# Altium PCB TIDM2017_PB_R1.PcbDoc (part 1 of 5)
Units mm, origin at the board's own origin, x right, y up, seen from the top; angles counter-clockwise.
Board outline 120 x 147.5 mm, 4 copper layers (Top Layer, L2, L3, Bottom Layer), stack 1.413 mm thick; 117 components, 53 nets, 3137 pads, 96 vias.
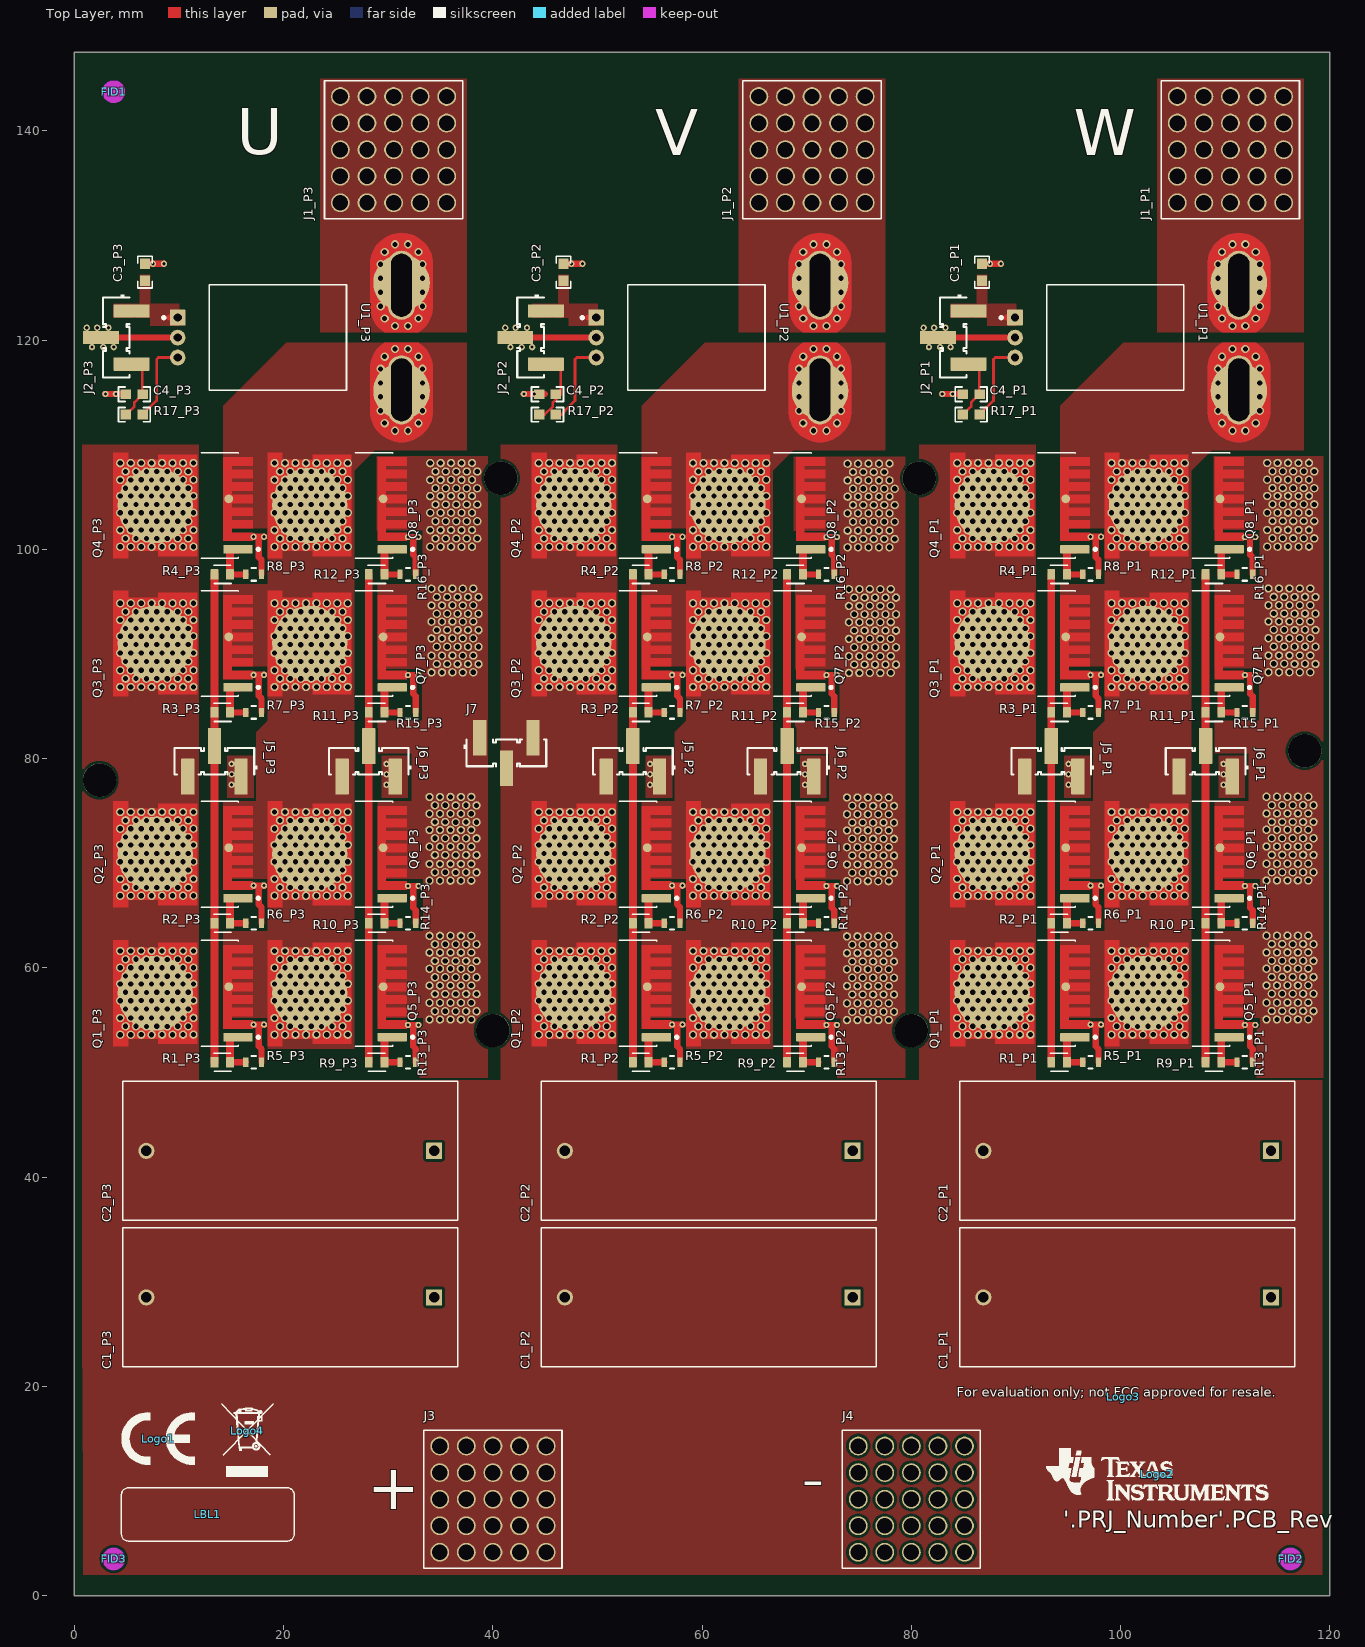
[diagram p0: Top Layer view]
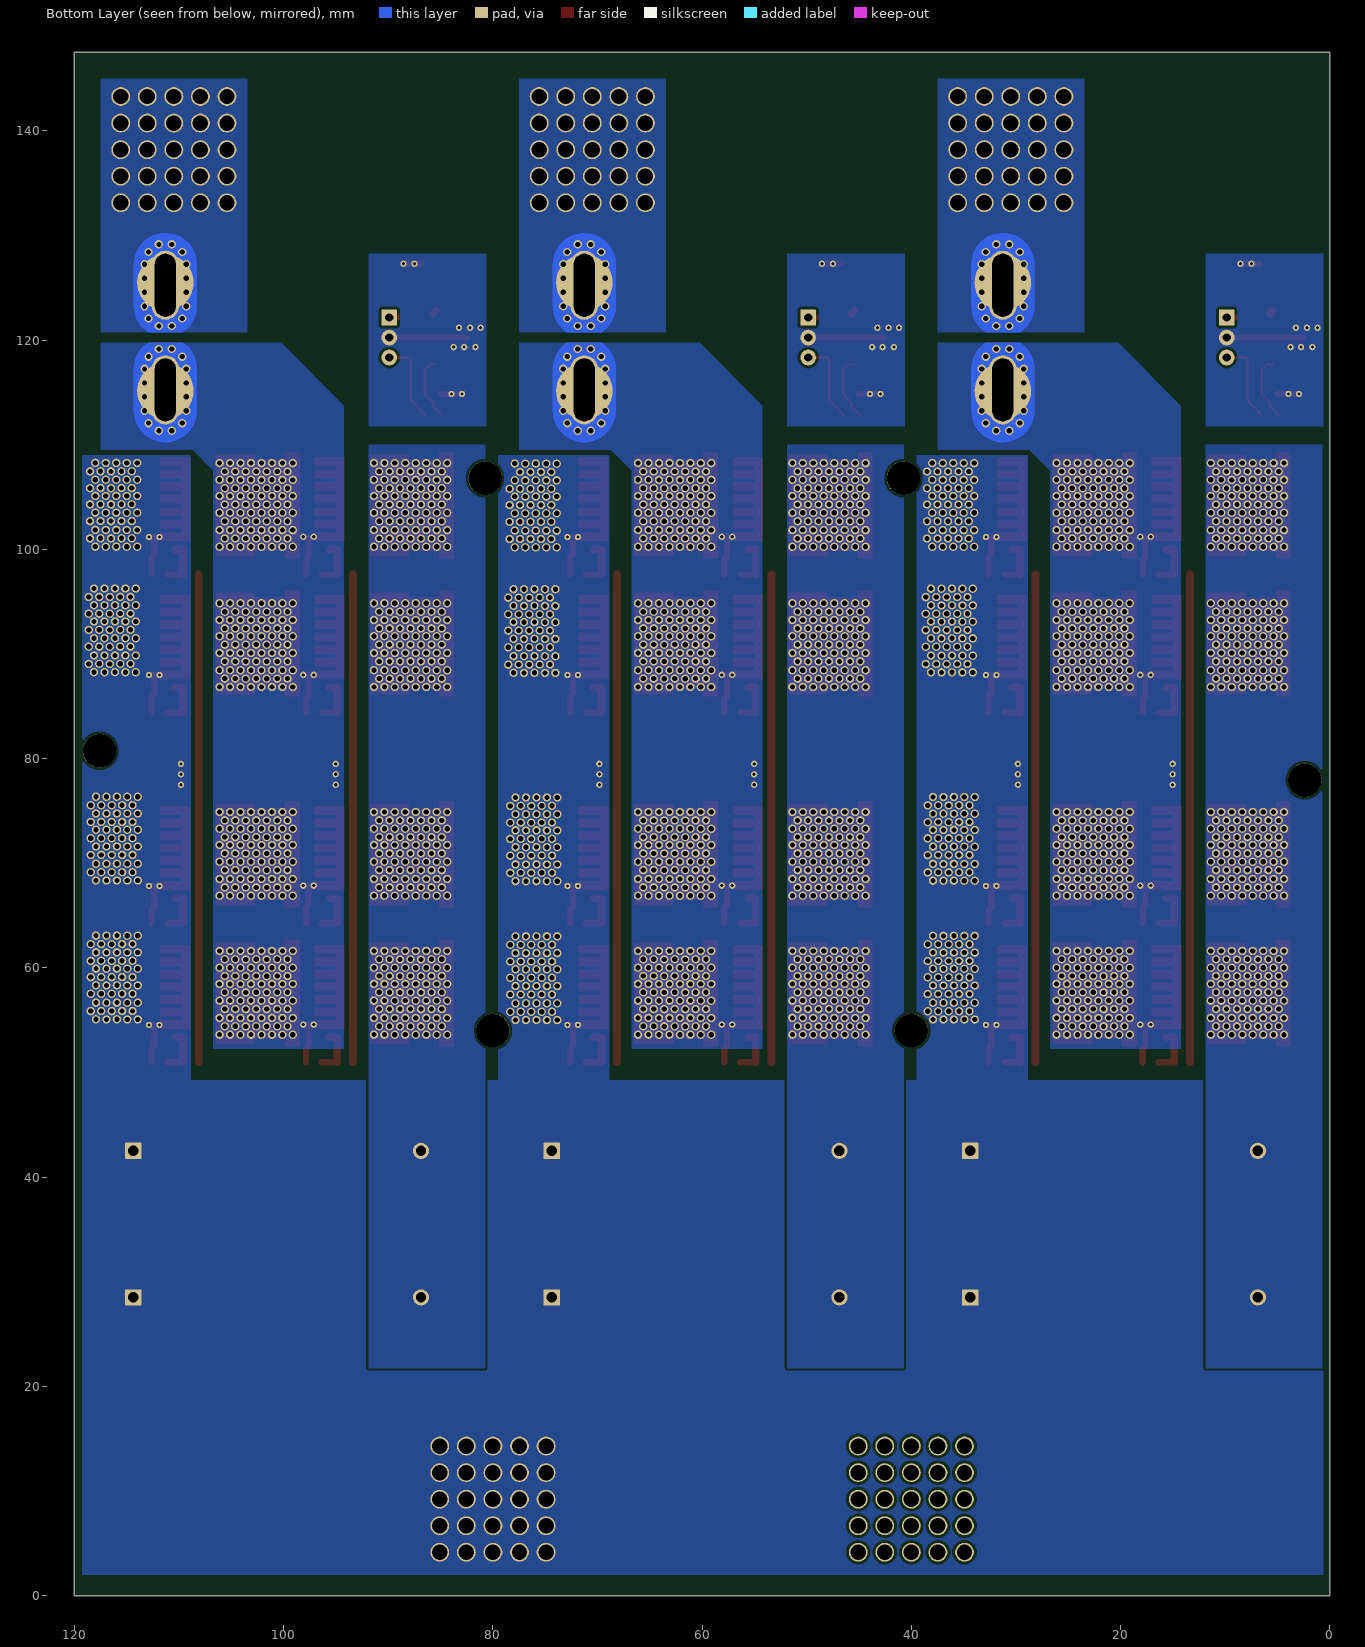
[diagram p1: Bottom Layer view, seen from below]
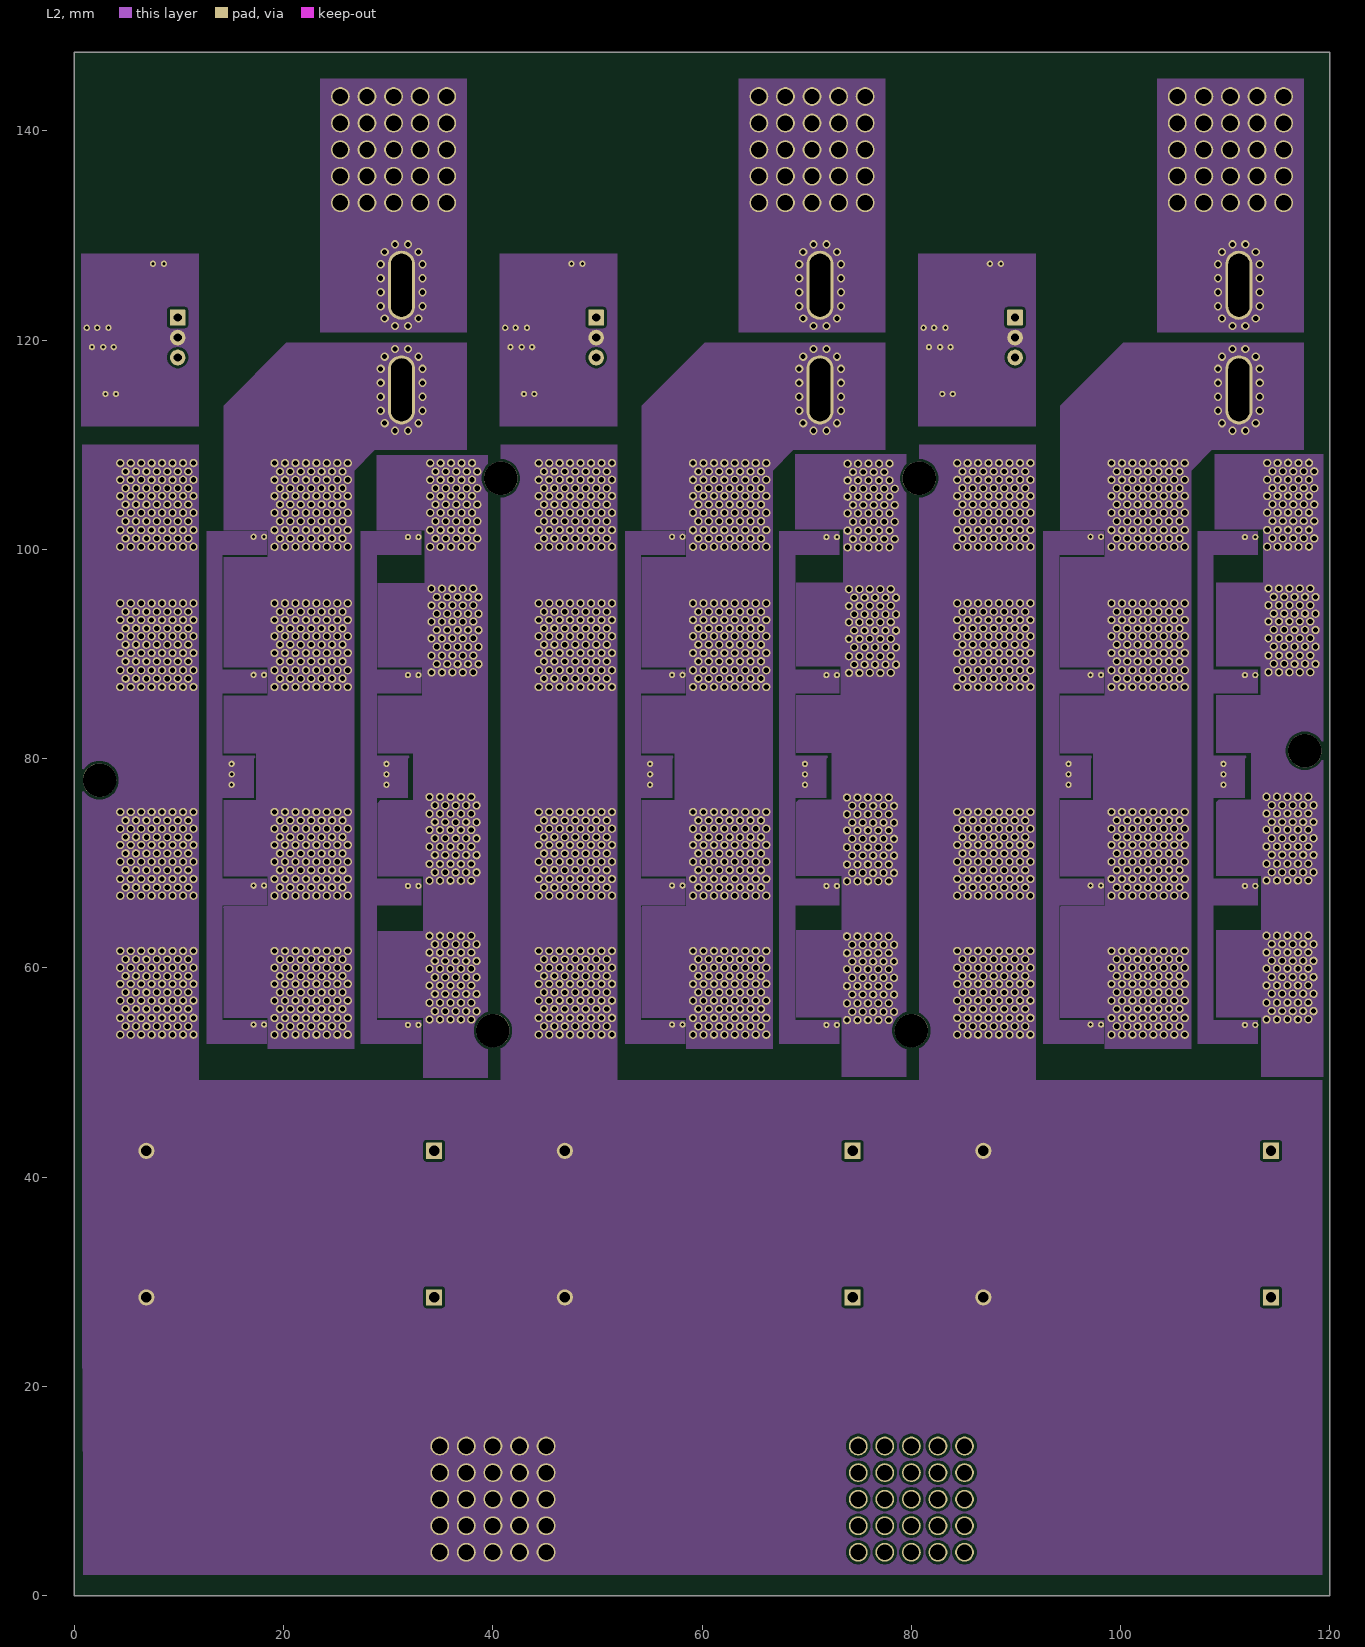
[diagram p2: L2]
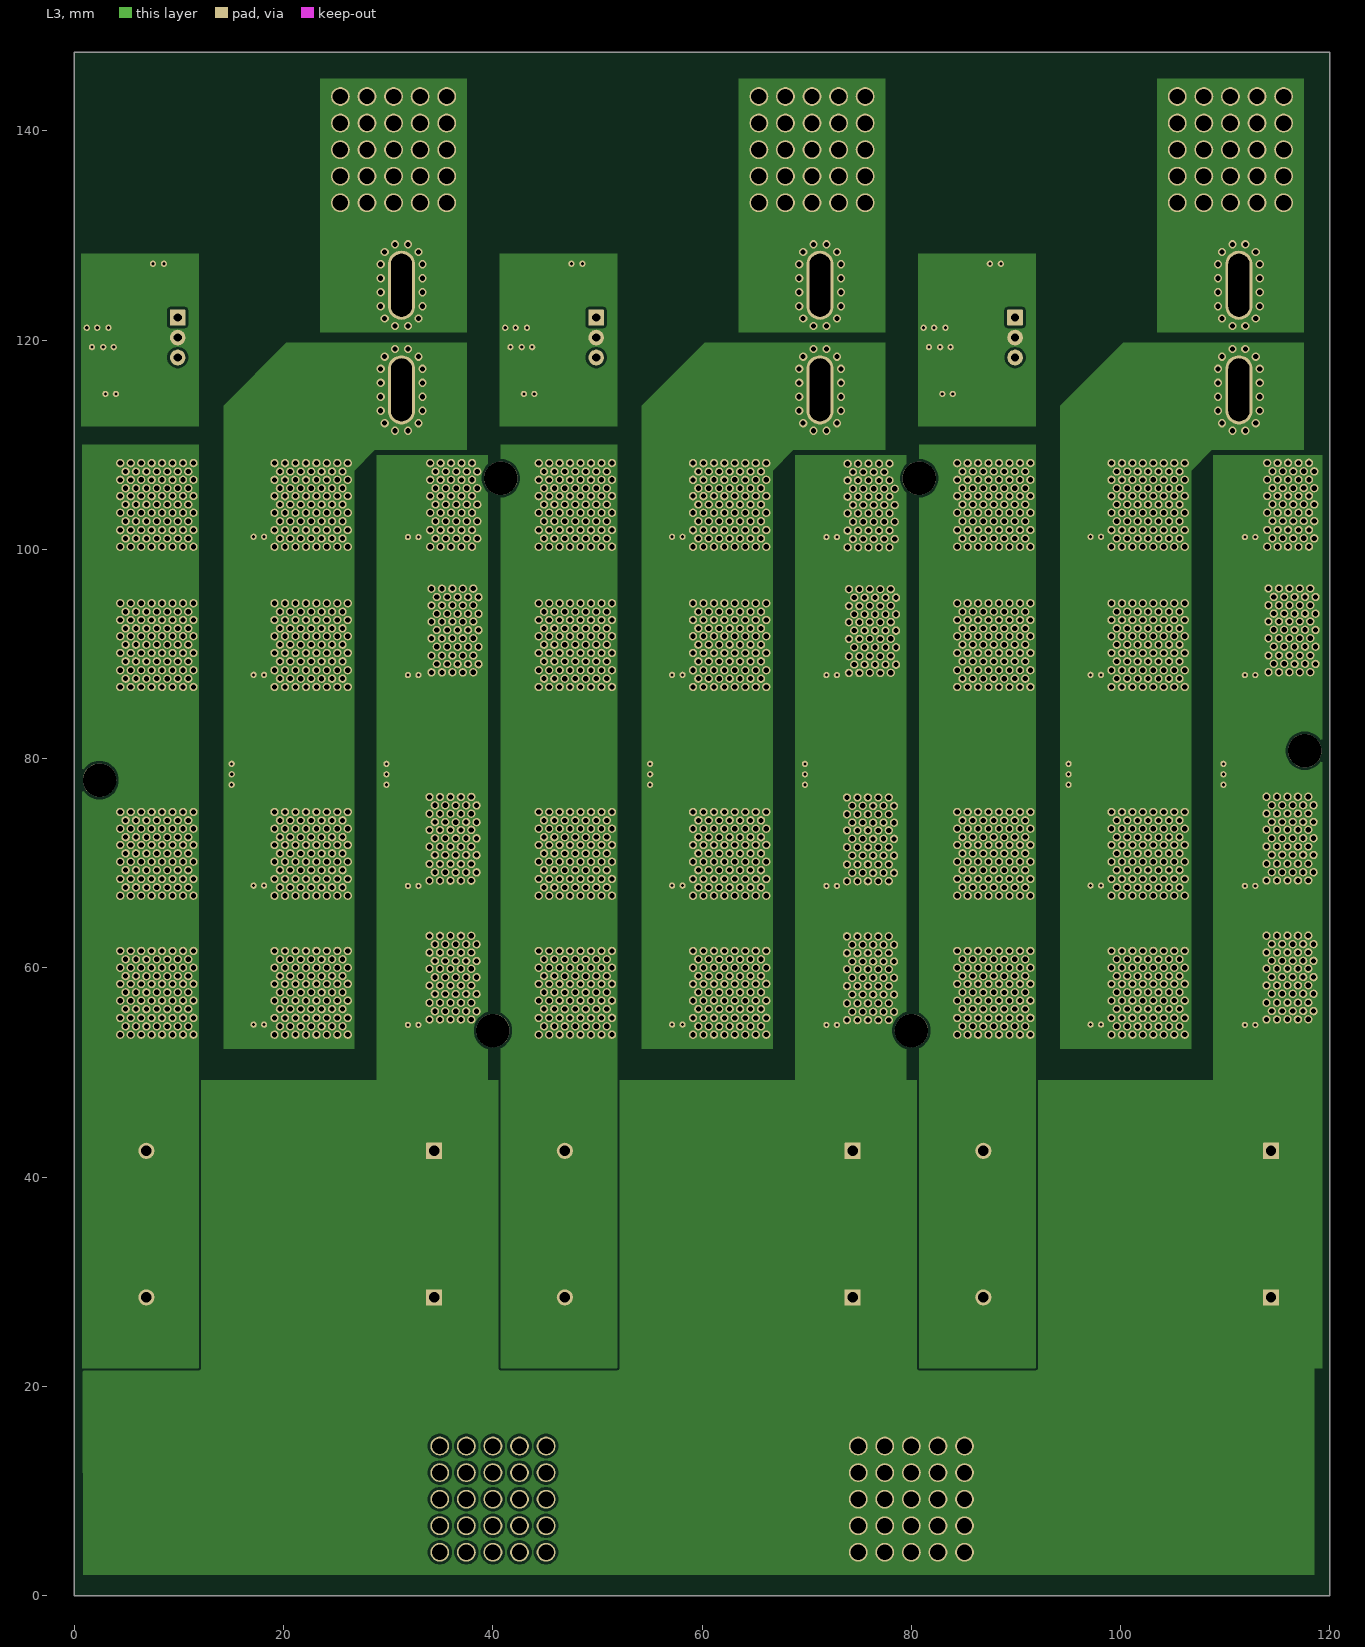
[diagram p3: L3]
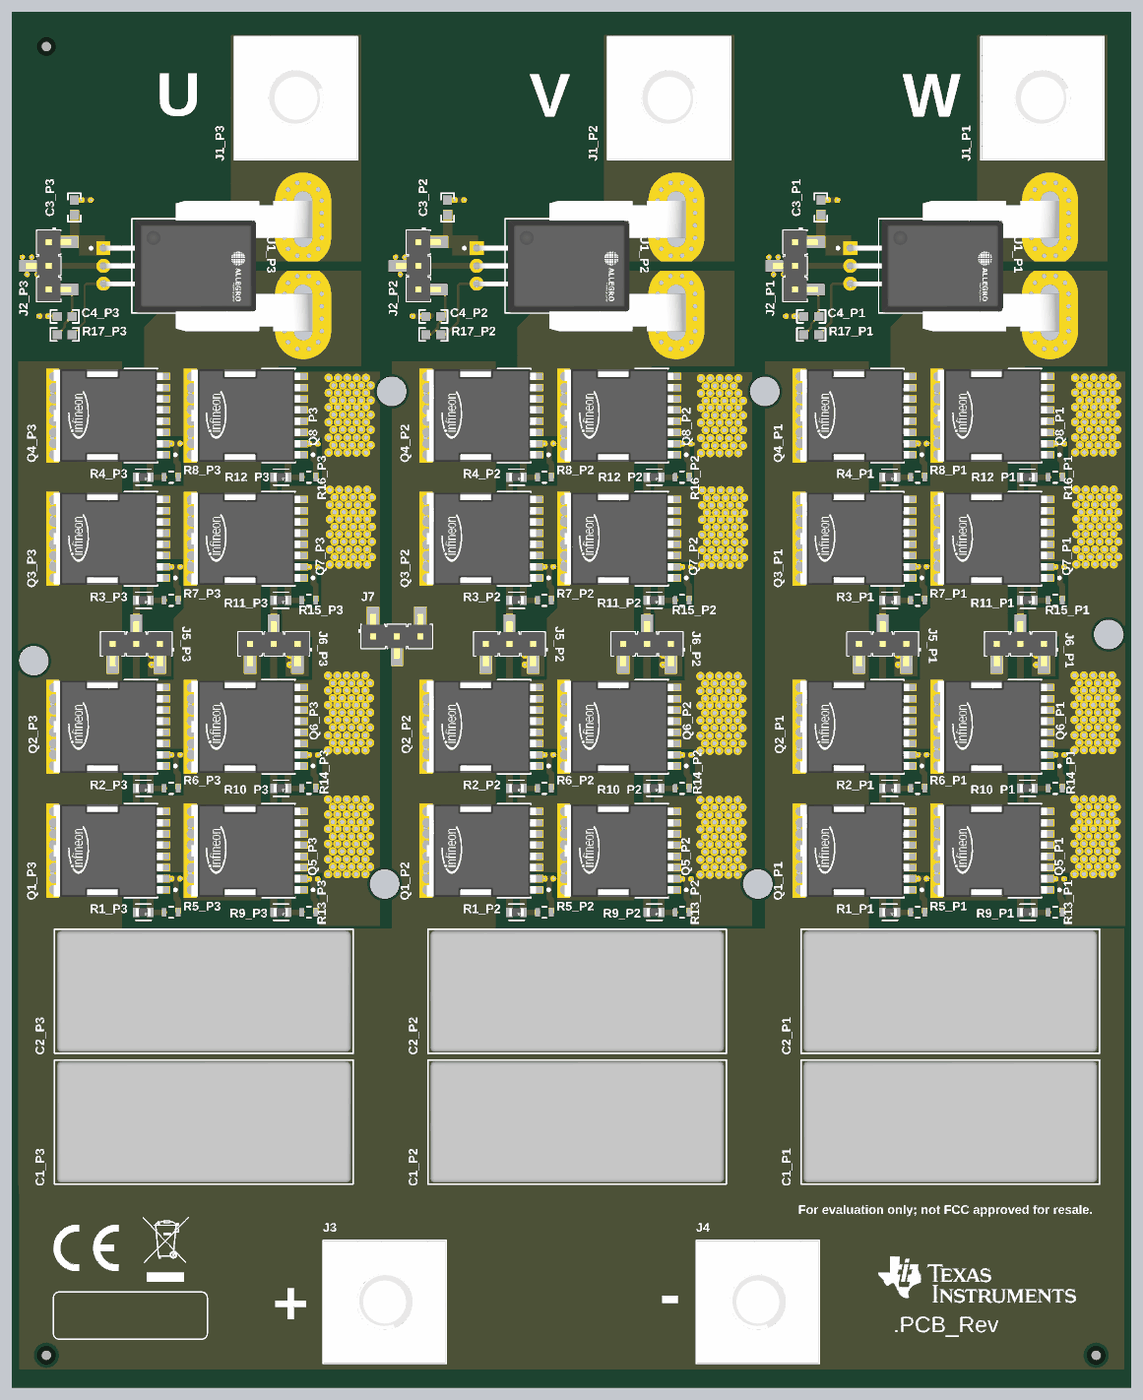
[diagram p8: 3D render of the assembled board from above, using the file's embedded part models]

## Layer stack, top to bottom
Top Solder: solder mask 0.0102, Solder Resist, Dk 3.5
Top Layer: signal copper 0.07
Dielectric 1: prepreg 0.0711, PP-006, Dk 4.1
L2: signal copper 0.07
Dielectric1: core 0.9906, FR-4 High Tg, Dk 4.8
L3: signal copper 0.07
Dielectric 2: prepreg 0.0711, PP-006, Dk 4.1
Bottom Layer: signal copper 0.07
Bottom Solder: solder mask 0.0102, Solder Resist, Dk 3.5

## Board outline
0,0 0,147.5 120,147.5 120,0

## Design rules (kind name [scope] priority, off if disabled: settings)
AcuteAngle [All] p1: minimum=4.50000000000000E+0001 checktracksonly=FALSE
AssemblyTestPointUsage [All] p1: valid=2
BoardOutlineClearance BoardOutlineClearance_MountingHoles [OnCopper and InComponentClass('Mounting Holes')] p1: gap=1 ignorepadtopadclearanceinfootprint=FALSE
BoardOutlineClearance BoardOutlineClearance_Poly [OnCopper and IsPoly] p2: gap=0.635 ignorepadtopadclearanceinfootprint=FALSE
BoardOutlineClearance [OnCopper and Not InComponentClass('Logo') and not InComponentClass('FiducialMark') and not InRegion(1000,500,4000,800) and not InPoly] p3: gap=1.016 ignorepadtopadclearanceinfootprint=FALSE
Clearance Clearance_Keepouts [((IsTrack Or IsArc) And Not InPoly) And IsFree and IsKeepOut vs ((IsTrack Or IsArc) And Not InPoly) And IsFree and IsKeepOut] p1: gap=0 ignorepadtopadclearanceinfootprint=FALSE
Clearance Clearance_Poly [InPolygon] p2: gap=0.254 ignorepadtopadclearanceinfootprint=TRUE
Clearance Clearance_FiducialMark [IsKeepOut and InComponentClass('FiducialMark') vs IsPad and InComponentClass('FiducialMark')] p3: gap=0 ignorepadtopadclearanceinfootprint=FALSE
Clearance [All] p4: gap=0.2 ignorepadtopadclearanceinfootprint=TRUE
ComponentClearance ComponentClearance_MountingHoles_FiducialMarks [InComponentClass('Mounting Holes') vs InComponentClass('FiducialMark')] p1: gap=1.27 collisioncheckmode=3 verticalgap=0.254 showdistances=FALSE
ComponentClearance ComponentClearance_Shunt [InComponentClass('Header') vs InComponentClass('Shunt')] p2: gap=0 collisioncheckmode=3 verticalgap=0 showdistances=FALSE
ComponentClearance ComponentClearance_Logo [InComponentClass('Logo')] p3: gap=0.762 collisioncheckmode=3 verticalgap=0.254 showdistances=FALSE
ComponentClearance ComponentClearance_ScrewToNut [(HasFootprint('NY PMS 440 0025 PH')) vs (HasFootprint('Keystone_1902C'))] p4: gap=0.127 collisioncheckmode=3 verticalgap=0.254 showdistances=FALSE
ComponentClearance ComponentClearance_MountingHoles [InComponentClass('Mounting Holes')] p5: gap=2.54 collisioncheckmode=3 verticalgap=2540 showdistances=FALSE
ComponentClearance ComponentClearance_SmallPassives [HasFootprint('0201*') or HasFootprint('0402*') or HasFootprint('0508') or HasFootprint('0603*') or HasFootprint('0612') or HasFootprint('0805*') or HasFootprint('0815*') or HasFootprint('0830*') or HasFootprint('1206*') or HasFootprint('1210*') or HasFootprint('1808*') or HasFootprint('1812*') or HasFootprint('1825*') or HasFootprint('2010*') or HasFootprint('2220*') or HasFootprint('2225*') or HasFootprint('2512*') or HasFootprint('2728*') or HasFootprint('3518*') vs HasFootprint('0201*') or HasFootprint('0402*') or HasFootprint('0508') or HasFootprint('0603*') or HasFootprint('0612') or HasFootprint('0805*') or HasFootprint('0815*') or HasFootprint('0830*') or HasFootprint('1206*') or HasFootprint('1210*') or HasFootprint('1808*') or HasFootprint('1812*') or HasFootprint('1825*') or HasFootprint('2010*') or HasFootprint('2220*') or HasFootprint('2225*') or HasFootprint('2512*') or HasFootprint('2728*') or HasFootprint('3518*')] p6: gap=0.38 collisioncheckmode=3 verticalgap=0.254 showdistances=FALSE
ComponentClearance ComponentClearance_THtoSMT [IsThruComponent vs IsSMTComponent] p7: gap=0.762 collisioncheckmode=3 verticalgap=0.762 showdistances=FALSE
ComponentClearance ComponentClearance_THtoTH [IsThruComponent vs IsThruComponent] p8: gap=0.508 collisioncheckmode=3 verticalgap=0.762 showdistances=FALSE
ComponentClearance [All] p9: gap=0.508 collisioncheckmode=3 verticalgap=0.254 showdistances=FALSE
DiffPairsRouting [All] p1: maxlimit=2.54 minlimit=0.254 mostfreqgap=0.254 toplayer_minwidth=0.381 toplayer_maxwidth=0.381 toplayer_prefwidth=0.381 midlayer1_minwidth=0.381 midlayer1_maxwidth=0.381 midlayer1_prefwidth=0.381 midlayer2_minwidth=0.381 midlayer2_maxwidth=0.381 midlayer2_prefwidth=0.381 bottomlayer_minwidth=0.381 bottomlayer_maxwidth=0.381 bottomlayer_prefwidth=0.381 maxuncoupledlength=25.4
FabricationTestPointUsage TestPointUsage [All] p1: valid=2 allowmultiple=FALSE
FabricationTestpoint Testpoint [All] p1: side=3 testpointundercomponent=TRUE minsize=1.016 maxsize=2.54 preferedsize=1.524 minholesize=0 maxholesize=1.016 preferedholesize=0.813 testpointgrid=0.025 allowsidetop=TRUE allowsidebottom=TRUE usegrid=TRUE gridtolerance=0
FanoutControl Fanout_LCC [IsLCC] p1: bgadir=Out bgaviamode=Centered fanoutstyle=Auto fanoutdirection=Alternating viagrid=0.025 // Fanout_LCC (Default Rule)
FanoutControl Fanout_BGA [IsBGA] p2: bgadir=Out bgaviamode=Centered fanoutstyle=Auto fanoutdirection=Alternating viagrid=0.025 // Fanout_BGA (Default Rule)
FanoutControl Fanout_Default [All] p4: bgadir=Out bgaviamode=Centered fanoutstyle=Auto fanoutdirection=Alternating viagrid=0.025 // Fanout_Default (Default Rule)
FanoutControl Fanout_Small [(CompPinCount < 5)] p5: bgadir=Out bgaviamode=Centered fanoutstyle=Auto fanoutdirection=OutThenIn viagrid=0.025 // Fanout_Small (Default Rule)
HoleSize [All] p1: absolutevalues=TRUE maxlimit=6.375 minlimit=0.2 maxpercent=80.000 minpercent=20.000
MinimumAnnularRing MinimumAnnularRing_ThermalPadVias [IsVia and InAnyComponent] p1: minimumring=0.15
MinimumAnnularRing [All] p2: minimumring=0.2
MinimumSolderMaskSliver MinimumSolderMaskSliver_Logo [InComponentClass('Logo') vs InComponentClass('Logo')] p1: minsoldermaskwidth=0.018
MinimumSolderMaskSliver [All] p2: minsoldermaskwidth=0.1
PlaneConnect [All] p1: planeconnectstyle=Relief reliefexpansion=0.254 reliefentries=4 reliefconductorwidth=0.254 reliefairgap=0.254
PolygonConnect [All] p1: connectstyle=Direct reliefconductorwidth=0.254 reliefentries=4 polygonreliefangle="90 Angle" airgapwidth=0.254
RoomDefinition P3 [InComponentClass('P3')] p1: confinementstyle=ConfineIn formatcopy=TRUE lockcomponents=FALSE outline 40,17.5 40,147.5 0,147.5 0,17.5
RoomDefinition P1 [InComponentClass('P1')] p2: confinementstyle=ConfineIn formatcopy=TRUE lockcomponents=FALSE outline 120,17.5 120,147.5 80,147.5 80,17.5
RoomDefinition P2 [InComponentClass('P2')] p3: confinementstyle=ConfineIn formatcopy=TRUE lockcomponents=FALSE outline 80,17.5 80,147.5 40,147.5 40,17.5
RoutingLayers [All] p1: top layer_v5=TRUE mid layer 1_v5=FALSE mid layer 2_v5=FALSE bottom layer_v5=TRUE
RoutingVias ThermalPadVias [IsVia and InAnyComponent] p1: holewidth=0.2 width=0.5 viastyle="Through Hole" minholewidth=0.2 minwidth=0.5 maxholewidth=0.33 maxwidth=0.6
RoutingVias [All] p2: holewidth=0.406 width=0.864 viastyle="Through Hole" minholewidth=0.2 minwidth=0.61 maxholewidth=1.016 maxwidth=1.651
SilkToBoardRegionClearance [Not ((IsComment or IsDesignator) And (Hide <> 'False')) and not InRegion(1000,500,4000,800)] p1:
SilkToSilkClearance SilkToSilkClearance_Pb-FreeLogo [(HasFootprint('Pb-Free_Overlay_Medium') OR HasFootprint('Pb-Free_Overlay_Small')) vs (HasFootprint('Pb-Free_Overlay_Medium') OR HasFootprint('Pb-Free_Overlay_Small'))] p1: silktosilkclearance=0
SilkToSilkClearance [All] p2: silktosilkclearance=0.1
SilkToSolderMaskClearance SilkToComponentPadClearance [(IsPad or IsFill or IsRegion) and InAnycomponent] p1: minsilkscreentomaskgap=0.127 clearancetoexposedcopper=TRUE
SilkToSolderMaskClearance "Silk to Solder Mask Opening" [All] p2: minsilkscreentomaskgap=0.1 clearancetoexposedcopper=FALSE
SolderMaskExpansion [All] p1: expansion=0.05 istentingtop=FALSE
UnRoutedNet [All] p1: checkbadconnections=TRUE
Width [All] p1: maxlimit=2.54 minlimit=0.152 preferedwidth=0.254 checkconnectedcopper=TRUE
13 further rules are at their usual default settings.

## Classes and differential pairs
component class Logo: Logo2
component class Label: LBL1
component class FiducialMark: FID1 FID2 FID3
component class Designator: !PCB1 FID1 FID2 FID3 LBL1 Logo1 Logo2 Logo3 Logo4 ZZ1 ZZ2 ZZ3 ZZ4
component class AssemblyNote: ZZ1 ZZ2 ZZ3 ZZ4
net class J7_Nets: D_HS_P1 NetJ7_2 S_LS_P1
channel class TDIM_2017_Phase_Leg: P1 P2 P3
net class U1_P3_Nets: +5V_P3 D_LS_P3 NetC3_P3_2 NetJ1_P3_1 NetR17_P3_2
net class U1_P2_Nets: +5V_P2 D_LS_P2 NetC3_P2_2 NetJ1_P2_1 NetR17_P2_2
net class U1_P1_Nets: +5V_P1 D_LS_P1 NetC3_P1_2 NetJ1_P1_1 NetR17_P1_2
net class R17_P3_Nets: IOUT_P3 NetR17_P3_2
net class R17_P2_Nets: IOUT_P2 NetR17_P2_2
net class R17_P1_Nets: IOUT_P1 NetR17_P1_2
net class R16_P3_Nets: NetQ8_P3_1 S_LS_P1
net class R16_P2_Nets: NetQ8_P2_1 S_LS_P1
net class R16_P1_Nets: NetQ8_P1_1 S_LS_P1
net class R15_P3_Nets: NetQ7_P3_1 S_LS_P1
net class R15_P2_Nets: NetQ7_P2_1 S_LS_P1
net class R15_P1_Nets: NetQ7_P1_1 S_LS_P1
net class R14_P3_Nets: NetQ6_P3_1 S_LS_P1
net class R14_P2_Nets: NetQ6_P2_1 S_LS_P1
net class R14_P1_Nets: NetQ6_P1_1 S_LS_P1
net class R13_P3_Nets: NetQ5_P3_1 S_LS_P1
net class R13_P2_Nets: NetQ5_P2_1 S_LS_P1
net class R13_P1_Nets: NetQ5_P1_1 S_LS_P1
net class R12_P3_Nets: G_LS_P3 NetQ8_P3_1
net class R12_P2_Nets: G_LS_P2 NetQ8_P2_1
net class R12_P1_Nets: G_LS_P1 NetQ8_P1_1
net class R11_P3_Nets: G_LS_P3 NetQ7_P3_1
net class R11_P2_Nets: G_LS_P2 NetQ7_P2_1
net class R11_P1_Nets: G_LS_P1 NetQ7_P1_1
net class R10_P3_Nets: G_LS_P3 NetQ6_P3_1
net class R10_P2_Nets: G_LS_P2 NetQ6_P2_1
net class R10_P1_Nets: G_LS_P1 NetQ6_P1_1
net class R9_P3_Nets: G_LS_P3 NetQ5_P3_1
net class R9_P2_Nets: G_LS_P2 NetQ5_P2_1
net class R9_P1_Nets: G_LS_P1 NetQ5_P1_1
net class R8_P3_Nets: D_LS_P3 NetQ4_P3_1
net class R8_P2_Nets: D_LS_P2 NetQ4_P2_1
net class R8_P1_Nets: D_LS_P1 NetQ4_P1_1
net class R7_P3_Nets: D_LS_P3 NetQ3_P3_1
net class R7_P2_Nets: D_LS_P2 NetQ3_P2_1
net class R7_P1_Nets: D_LS_P1 NetQ3_P1_1
net class R6_P3_Nets: D_LS_P3 NetQ2_P3_1
net class R6_P2_Nets: D_LS_P2 NetQ2_P2_1
net class R6_P1_Nets: D_LS_P1 NetQ2_P1_1
net class R5_P3_Nets: D_LS_P3 NetQ1_P3_1
net class R5_P2_Nets: D_LS_P2 NetQ1_P2_1
net class R5_P1_Nets: D_LS_P1 NetQ1_P1_1
net class R4_P3_Nets: G_HS_P3 NetQ4_P3_1
net class R4_P2_Nets: G_HS_P2 NetQ4_P2_1
net class R4_P1_Nets: G_HS_P1 NetQ4_P1_1
net class R3_P3_Nets: G_HS_P3 NetQ3_P3_1
net class R3_P2_Nets: G_HS_P2 NetQ3_P2_1
net class R3_P1_Nets: G_HS_P1 NetQ3_P1_1
net class R2_P3_Nets: G_HS_P3 NetQ2_P3_1
net class R2_P2_Nets: G_HS_P2 NetQ2_P2_1
net class R2_P1_Nets: G_HS_P1 NetQ2_P1_1
net class R1_P3_Nets: G_HS_P3 NetQ1_P3_1
net class R1_P2_Nets: G_HS_P2 NetQ1_P2_1
net class R1_P1_Nets: G_HS_P1 NetQ1_P1_1
net class Q8_P3_Nets: D_LS_P3 NetQ8_P3_1 S_LS_P1
net class Q8_P2_Nets: D_LS_P2 NetQ8_P2_1 S_LS_P1
net class Q8_P1_Nets: D_LS_P1 NetQ8_P1_1 S_LS_P1
net class Q7_P3_Nets: D_LS_P3 NetQ7_P3_1 S_LS_P1
net class Q7_P2_Nets: D_LS_P2 NetQ7_P2_1 S_LS_P1
net class Q7_P1_Nets: D_LS_P1 NetQ7_P1_1 S_LS_P1
net class Q6_P3_Nets: D_LS_P3 NetQ6_P3_1 S_LS_P1
net class Q6_P2_Nets: D_LS_P2 NetQ6_P2_1 S_LS_P1
net class Q6_P1_Nets: D_LS_P1 NetQ6_P1_1 S_LS_P1
net class Q5_P3_Nets: D_LS_P3 NetQ5_P3_1 S_LS_P1
net class Q5_P2_Nets: D_LS_P2 NetQ5_P2_1 S_LS_P1
net class Q5_P1_Nets: D_LS_P1 NetQ5_P1_1 S_LS_P1
net class Q4_P3_Nets: D_HS_P1 D_LS_P3 NetQ4_P3_1
net class Q4_P2_Nets: D_HS_P1 D_LS_P2 NetQ4_P2_1
net class Q4_P1_Nets: D_HS_P1 D_LS_P1 NetQ4_P1_1
net class Q3_P3_Nets: D_HS_P1 D_LS_P3 NetQ3_P3_1
net class Q3_P2_Nets: D_HS_P1 D_LS_P2 NetQ3_P2_1
net class Q3_P1_Nets: D_HS_P1 D_LS_P1 NetQ3_P1_1
net class Q2_P3_Nets: D_HS_P1 D_LS_P3 NetQ2_P3_1
net class Q2_P2_Nets: D_HS_P1 D_LS_P2 NetQ2_P2_1
net class Q2_P1_Nets: D_HS_P1 D_LS_P1 NetQ2_P1_1
net class Q1_P3_Nets: D_HS_P1 D_LS_P3 NetQ1_P3_1
net class Q1_P2_Nets: D_HS_P1 D_LS_P2 NetQ1_P2_1
net class Q1_P1_Nets: D_HS_P1 D_LS_P1 NetQ1_P1_1
net class P3_Nets: +5V_P3 D_HS_P1 D_LS_P3 G_HS_P3 G_LS_P3 GND_P3 IOUT_P3 NetC3_P3_2 NetJ1_P3_1 NetQ1_P3_1 NetQ2_P3_1 NetQ3_P3_1 NetQ4_P3_1 NetQ5_P3_1 NetQ6_P3_1 NetQ7_P3_1 NetQ8_P3_1 NetR17_P3_2 S_LS_P1
net class P2_Nets: +5V_P2 D_HS_P1 D_LS_P2 G_HS_P2 G_LS_P2 GND_P2 IOUT_P2 NetC3_P2_2 NetJ1_P2_1 NetQ1_P2_1 NetQ2_P2_1 NetQ3_P2_1 NetQ4_P2_1 NetQ5_P2_1 NetQ6_P2_1 NetQ7_P2_1 NetQ8_P2_1 NetR17_P2_2 S_LS_P1
net class P1_Nets: +5V_P1 D_HS_P1 D_LS_P1 G_HS_P1 G_LS_P1 GND_P1 IOUT_P1 NetC3_P1_2 NetJ1_P1_1 NetQ1_P1_1 NetQ2_P1_1 NetQ3_P1_1 NetQ4_P1_1 NetQ5_P1_1 NetQ6_P1_1 NetQ7_P1_1 NetQ8_P1_1 NetR17_P1_2 S_LS_P1
net class J6_P3_Nets: D_LS_P3 G_LS_P3 S_LS_P1
net class J6_P2_Nets: D_LS_P2 G_LS_P2 S_LS_P1
net class J6_P1_Nets: D_LS_P1 G_LS_P1 S_LS_P1
net class J5_P3_Nets: D_HS_P1 D_LS_P3 G_HS_P3
net class J5_P2_Nets: D_HS_P1 D_LS_P2 G_HS_P2
net class J5_P1_Nets: D_HS_P1 D_LS_P1 G_HS_P1
net class J2_P3_Nets: +5V_P3 GND_P3 IOUT_P3
net class J2_P2_Nets: +5V_P2 GND_P2 IOUT_P2
net class J2_P1_Nets: +5V_P1 GND_P1 IOUT_P1
net class J1_P3_Nets: NetJ1_P3_1
net class J1_P2_Nets: NetJ1_P2_1
net class J1_P1_Nets: NetJ1_P1_1
net class C4_P3_Nets: IOUT_P3 NetC3_P3_2
net class C4_P2_Nets: IOUT_P2 NetC3_P2_2
net class C4_P1_Nets: IOUT_P1 NetC3_P1_2
net class C3_P3_Nets: +5V_P3 NetC3_P3_2
net class C3_P2_Nets: +5V_P2 NetC3_P2_2
net class C3_P1_Nets: +5V_P1 NetC3_P1_2
net class C2_P3_Nets: D_HS_P1 S_LS_P1
net class C2_P2_Nets: D_HS_P1 S_LS_P1
net class C2_P1_Nets: D_HS_P1 S_LS_P1
net class C1_P3_Nets: D_HS_P1 S_LS_P1
net class C1_P2_Nets: D_HS_P1 S_LS_P1
net class C1_P1_Nets: D_HS_P1 S_LS_P1
component class P3: C1_P3 C2_P3 C3_P3 C4_P3 J1_P3 J2_P3 J5_P3 J6_P3 Q1_P3 Q2_P3 Q3_P3 Q4_P3 Q5_P3 Q6_P3 Q7_P3 Q8_P3 R1_P3 R2_P3 R3_P3 R4_P3 R5_P3 R6_P3 R7_P3 R8_P3 R9_P3 R10_P3 R11_P3 R12_P3 R13_P3 R14_P3 R15_P3 R16_P3 R17_P3 U1_P3
component class P2: C1_P2 C2_P2 C3_P2 C4_P2 J1_P2 J2_P2 J5_P2 J6_P2 Q1_P2 Q2_P2 Q3_P2 Q4_P2 Q5_P2 Q6_P2 Q7_P2 Q8_P2 R1_P2 R2_P2 R3_P2 R4_P2 R5_P2 R6_P2 R7_P2 R8_P2 R9_P2 R10_P2 R11_P2 R12_P2 R13_P2 R14_P2 R15_P2 R16_P2 R17_P2 U1_P2
component class P1: C1_P1 C2_P1 C3_P1 C4_P1 J1_P1 J2_P1 J5_P1 J6_P1 Q1_P1 Q2_P1 Q3_P1 Q4_P1 Q5_P1 Q6_P1 Q7_P1 Q8_P1 R1_P1 R2_P1 R3_P1 R4_P1 R5_P1 R6_P1 R7_P1 R8_P1 R9_P1 R10_P1 R11_P1 R12_P1 R13_P1 R14_P1 R15_P1 R16_P1 R17_P1 U1_P1
net class J4_Nets: S_LS_P1
net class J3_Nets: D_HS_P1
component class TIDM2017_PB_R1: J3 J4 J7
component class Header: J2_P1 J2_P2 J2_P3 J5_P1 J5_P2 J5_P3 J6_P1 J6_P2 J6_P3 J7

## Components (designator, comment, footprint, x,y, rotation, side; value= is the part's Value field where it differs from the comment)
C1_P1 "C4AQCBU4560A1XJ" FP-C4AQCBU4560A1XJ_RADIAL-MFG 100.626,28.5 r180 top value=5.6µF (schematic designator C1)
C1_P2 "C4AQCBU4560A1XJ" FP-C4AQCBU4560A1XJ_RADIAL-MFG 60.626,28.5 r180 top value=5.6µF (schematic designator C1)
C1_P3 "C4AQCBU4560A1XJ" FP-C4AQCBU4560A1XJ_RADIAL-MFG 20.626,28.5 r180 top value=5.6µF (schematic designator C1)
C2_P1 "C4AQCBU4560A1XJ" FP-C4AQCBU4560A1XJ_RADIAL-MFG 100.626,42.508 r180 top value=5.6µF (schematic designator C2)
C2_P2 "C4AQCBU4560A1XJ" FP-C4AQCBU4560A1XJ_RADIAL-MFG 60.626,42.508 r180 top value=5.6µF (schematic designator C2)
C2_P3 "C4AQCBU4560A1XJ" FP-C4AQCBU4560A1XJ_RADIAL-MFG 20.626,42.508 r180 top value=5.6µF (schematic designator C2)
C3_P1 "06035C104KAT2A" 0603 86.75,126.5 r90 top value=0.1uF (schematic designator C3)
C3_P2 "06035C104KAT2A" 0603 46.75,126.5 r90 top value=0.1uF (schematic designator C3)
C3_P3 "06035C104KAT2A" 0603 6.746,126.5 r90 top value=0.1uF (schematic designator C3)
C4_P1 "06035C104KAT2A" 0603 85.72,114.828 r0 top value=0.1uF (schematic designator C4)
C4_P2 "06035C104KAT2A" 0603 45.21,114.828 r0 top value=0.1uF (schematic designator C4)
C4_P3 "06035C104KAT2A" 0603 5.72,114.828 r0 top value=0.1uF (schematic designator C4)
FID1 "Fiducial" Fiducial10-20 3.75,143.75 r0 top
FID2 "Fiducial" Fiducial10-20 116.25,3.5 r0 top
FID3 "Fiducial" Fiducial10-20 3.75,3.5 r0 top
J1_P1 "7461098" FP-7461098_TERM_REDCUBE_M6-MFG 110.5,138.21 r90 top (schematic designator J1)
J1_P2 "7461098" FP-7461098_TERM_REDCUBE_M6-MFG 70.5,138.21 r90 top (schematic designator J1)
J1_P3 "7461098" FP-7461098_TERM_REDCUBE_M6-MFG 30.5,138.21 r90 top (schematic designator J1)
J2_P1 "TSM-103-01-L-SV-P-TR" Samtec_TSM-103-01-x-SV-P 84,120.25 r270 top (schematic designator J2)
J2_P2 "TSM-103-01-L-SV-P-TR" Samtec_TSM-103-01-x-SV-P 43.597,120.25 r270 top (schematic designator J2)
J2_P3 "TSM-103-01-L-SV-P-TR" Samtec_TSM-103-01-x-SV-P 4,120.25 r270 top (schematic designator J2)
J3 "7461098" FP-7461098_TERM_REDCUBE_M6-MFG 40,9.21 r0 top
J4 "7461098" FP-7461098_TERM_REDCUBE_M6-MFG 80,9.21 r0 top
J5_P1 "TSM-103-01-L-SV-P-TR" Samtec_TSM-103-01-x-SV-P 93.376,79.739 r180 top (schematic designator J5)
J5_P2 "TSM-103-01-L-SV-P-TR" Samtec_TSM-103-01-x-SV-P 53.376,79.739 r180 top (schematic designator J5)
J5_P3 "TSM-103-01-L-SV-P-TR" Samtec_TSM-103-01-x-SV-P 13.376,79.739 r180 top (schematic designator J5)
J6_P1 "TSM-103-01-L-SV-P-TR" Samtec_TSM-103-01-x-SV-P 108.126,79.739 r180 top (schematic designator J6)
J6_P2 "TSM-103-01-L-SV-P-TR" Samtec_TSM-103-01-x-SV-P 68.126,79.739 r180 top (schematic designator J6)
J6_P3 "TSM-103-01-L-SV-P-TR" Samtec_TSM-103-01-x-SV-P 28.126,79.739 r180 top (schematic designator J6)
J7 "TSM-103-01-L-SV-P-TR" Samtec_TSM-103-01-x-SV-P 41.29,80.54 r0 top
LBL1 "THT-14-423-10" Label_650x200 12.75,7.75 r0 top
Logo1 "CE Mark" CE_Mark_5mm 8,15 r0 top
Logo2 "Texas Instruments" TI_Stacked_Overlay_Small 103.5,11.598 r0 top
Logo3 "FCC disclaimer" FCC_disclaimer 100.25,19 r0 top
Logo4 "WEEE logo" WEEE_Minimum 16.5,15.75 r0 top
Q1_P1 "IAUT300N10S5N015ATMA1" FP-IAUT300N10S5N015ATMA1_HSOF-8-MFG 90.376,57.572 r90 top (schematic designator Q1)
Q1_P2 "IAUT300N10S5N015ATMA1" FP-IAUT300N10S5N015ATMA1_HSOF-8-MFG 50.376,57.572 r90 top (schematic designator Q1)
Q1_P3 "IAUT300N10S5N015ATMA1" FP-IAUT300N10S5N015ATMA1_HSOF-8-MFG 10.376,57.572 r90 top (schematic designator Q1)
Q2_P1 "IAUT300N10S5N015ATMA1" FP-IAUT300N10S5N015ATMA1_HSOF-8-MFG 90.376,70.855 r90 top (schematic designator Q2)
Q2_P2 "IAUT300N10S5N015ATMA1" FP-IAUT300N10S5N015ATMA1_HSOF-8-MFG 50.376,70.855 r90 top (schematic designator Q2)
Q2_P3 "IAUT300N10S5N015ATMA1" FP-IAUT300N10S5N015ATMA1_HSOF-8-MFG 10.376,70.855 r90 top (schematic designator Q2)
Q3_P1 "IAUT300N10S5N015ATMA1" FP-IAUT300N10S5N015ATMA1_HSOF-8-MFG 90.376,91.008 r90 top (schematic designator Q3)
Q3_P2 "IAUT300N10S5N015ATMA1" FP-IAUT300N10S5N015ATMA1_HSOF-8-MFG 50.376,91.008 r90 top (schematic designator Q3)
Q3_P3 "IAUT300N10S5N015ATMA1" FP-IAUT300N10S5N015ATMA1_HSOF-8-MFG 10.376,91.008 r90 top (schematic designator Q3)
Q4_P1 "IAUT300N10S5N015ATMA1" FP-IAUT300N10S5N015ATMA1_HSOF-8-MFG 90.376,104.203 r90 top (schematic designator Q4)
Q4_P2 "IAUT300N10S5N015ATMA1" FP-IAUT300N10S5N015ATMA1_HSOF-8-MFG 50.376,104.203 r90 top (schematic designator Q4)
Q4_P3 "IAUT300N10S5N015ATMA1" FP-IAUT300N10S5N015ATMA1_HSOF-8-MFG 10.376,104.203 r90 top (schematic designator Q4)
Q5_P1 "IAUT300N10S5N015ATMA1" FP-IAUT300N10S5N015ATMA1_HSOF-8-MFG 105.126,57.572 r90 top (schematic designator Q5)
Q5_P2 "IAUT300N10S5N015ATMA1" FP-IAUT300N10S5N015ATMA1_HSOF-8-MFG 65.126,57.572 r90 top (schematic designator Q5)
Q5_P3 "IAUT300N10S5N015ATMA1" FP-IAUT300N10S5N015ATMA1_HSOF-8-MFG 25.126,57.572 r90 top (schematic designator Q5)
Q6_P1 "IAUT300N10S5N015ATMA1" FP-IAUT300N10S5N015ATMA1_HSOF-8-MFG 105.126,70.855 r90 top (schematic designator Q6)
Q6_P2 "IAUT300N10S5N015ATMA1" FP-IAUT300N10S5N015ATMA1_HSOF-8-MFG 65.126,70.855 r90 top (schematic designator Q6)
Q6_P3 "IAUT300N10S5N015ATMA1" FP-IAUT300N10S5N015ATMA1_HSOF-8-MFG 25.126,70.855 r90 top (schematic designator Q6)
Q7_P1 "IAUT300N10S5N015ATMA1" FP-IAUT300N10S5N015ATMA1_HSOF-8-MFG 105.126,91.008 r90 top (schematic designator Q7)
Q7_P2 "IAUT300N10S5N015ATMA1" FP-IAUT300N10S5N015ATMA1_HSOF-8-MFG 65.126,91.008 r90 top (schematic designator Q7)
Q7_P3 "IAUT300N10S5N015ATMA1" FP-IAUT300N10S5N015ATMA1_HSOF-8-MFG 25.126,91.008 r90 top (schematic designator Q7)
Q8_P1 "IAUT300N10S5N015ATMA1" FP-IAUT300N10S5N015ATMA1_HSOF-8-MFG 105.126,104.203 r90 top (schematic designator Q8)
Q8_P2 "IAUT300N10S5N015ATMA1" FP-IAUT300N10S5N015ATMA1_HSOF-8-MFG 65.126,104.203 r90 top (schematic designator Q8)
Q8_P3 "IAUT300N10S5N015ATMA1" FP-IAUT300N10S5N015ATMA1_HSOF-8-MFG 25.126,104.203 r90 top (schematic designator Q8)
R1_P1 "RCS060310R0FKEA" FP-RCS060310R0FKEA_0603-MFG 94.126,50.975 r0 top value=10 (schematic designator R1)
R1_P2 "RCS060310R0FKEA" FP-RCS060310R0FKEA_0603-MFG 54.126,50.975 r0 top value=10 (schematic designator R1)
R1_P3 "RCS060310R0FKEA" FP-RCS060310R0FKEA_0603-MFG 14.126,50.975 r0 top value=10 (schematic designator R1)
R2_P1 "RCS060310R0FKEA" FP-RCS060310R0FKEA_0603-MFG 94.126,64.258 r0 top value=10 (schematic designator R2)
R2_P2 "RCS060310R0FKEA" FP-RCS060310R0FKEA_0603-MFG 54.126,64.258 r0 top value=10 (schematic designator R2)
R2_P3 "RCS060310R0FKEA" FP-RCS060310R0FKEA_0603-MFG 14.126,64.258 r0 top value=10 (schematic designator R2)
R3_P1 "RCS060310R0FKEA" FP-RCS060310R0FKEA_0603-MFG 94.126,84.411 r0 top value=10 (schematic designator R3)
R3_P2 "RCS060310R0FKEA" FP-RCS060310R0FKEA_0603-MFG 54.126,84.411 r0 top value=10 (schematic designator R3)
R3_P3 "RCS060310R0FKEA" FP-RCS060310R0FKEA_0603-MFG 14.126,84.411 r0 top value=10 (schematic designator R3)
R4_P1 "RCS060310R0FKEA" FP-RCS060310R0FKEA_0603-MFG 94.126,97.606 r0 top value=10 (schematic designator R4)
R4_P2 "RCS060310R0FKEA" FP-RCS060310R0FKEA_0603-MFG 54.126,97.606 r0 top value=10 (schematic designator R4)
R4_P3 "RCS060310R0FKEA" FP-RCS060310R0FKEA_0603-MFG 14.126,97.606 r0 top value=10 (schematic designator R4)
R5_P1 "TNPW060310K0BEEA" TNPW0603 97.126,50.975 r180 top value=10.0k (schematic designator R5)
R5_P2 "TNPW060310K0BEEA" TNPW0603 57.126,50.975 r180 top value=10.0k (schematic designator R5)
R5_P3 "TNPW060310K0BEEA" TNPW0603 17.126,50.975 r180 top value=10.0k (schematic designator R5)
R6_P1 "TNPW060310K0BEEA" TNPW0603 97.126,64.258 r180 top value=10.0k (schematic designator R6)
R6_P2 "TNPW060310K0BEEA" TNPW0603 57.126,64.258 r180 top value=10.0k (schematic designator R6)
R6_P3 "TNPW060310K0BEEA" TNPW0603 17.126,64.258 r180 top value=10.0k (schematic designator R6)
R7_P1 "TNPW060310K0BEEA" TNPW0603 97.126,84.411 r180 top value=10.0k (schematic designator R7)
R7_P2 "TNPW060310K0BEEA" TNPW0603 57.126,84.411 r180 top value=10.0k (schematic designator R7)
R7_P3 "TNPW060310K0BEEA" TNPW0603 17.126,84.411 r180 top value=10.0k (schematic designator R7)
R8_P1 "TNPW060310K0BEEA" TNPW0603 97.126,97.606 r180 top value=10.0k (schematic designator R8)
R8_P2 "TNPW060310K0BEEA" TNPW0603 57.126,97.606 r180 top value=10.0k (schematic designator R8)
R8_P3 "TNPW060310K0BEEA" TNPW0603 17.126,97.606 r180 top value=10.0k (schematic designator R8)
R9_P1 "RCS060310R0FKEA" FP-RCS060310R0FKEA_0603-MFG 108.876,50.975 r0 top value=10 (schematic designator R9)
R9_P2 "RCS060310R0FKEA" FP-RCS060310R0FKEA_0603-MFG 68.876,50.975 r0 top value=10 (schematic designator R9)
R9_P3 "RCS060310R0FKEA" FP-RCS060310R0FKEA_0603-MFG 28.876,50.975 r0 top value=10 (schematic designator R9)
R10_P1 "RCS060310R0FKEA" FP-RCS060310R0FKEA_0603-MFG 108.876,64.258 r0 top value=10 (schematic designator R10)
R10_P2 "RCS060310R0FKEA" FP-RCS060310R0FKEA_0603-MFG 68.876,64.258 r0 top value=10 (schematic designator R10)
R10_P3 "RCS060310R0FKEA" FP-RCS060310R0FKEA_0603-MFG 28.876,64.258 r0 top value=10 (schematic designator R10)
R11_P1 "RCS060310R0FKEA" FP-RCS060310R0FKEA_0603-MFG 108.876,84.411 r0 top value=10 (schematic designator R11)
R11_P2 "RCS060310R0FKEA" FP-RCS060310R0FKEA_0603-MFG 68.876,84.411 r0 top value=10 (schematic designator R11)
R11_P3 "RCS060310R0FKEA" FP-RCS060310R0FKEA_0603-MFG 28.876,84.411 r0 top value=10 (schematic designator R11)
R12_P1 "RCS060310R0FKEA" FP-RCS060310R0FKEA_0603-MFG 108.876,97.606 r0 top value=10 (schematic designator R12)
R12_P2 "RCS060310R0FKEA" FP-RCS060310R0FKEA_0603-MFG 68.876,97.606 r0 top value=10 (schematic designator R12)
R12_P3 "RCS060310R0FKEA" FP-RCS060310R0FKEA_0603-MFG 28.876,97.606 r0 top value=10 (schematic designator R12)
R13_P1 "TNPW060310K0BEEA" TNPW0603 111.876,50.975 r180 top value=10.0k (schematic designator R13)
R13_P2 "TNPW060310K0BEEA" TNPW0603 71.876,50.975 r180 top value=10.0k (schematic designator R13)
R13_P3 "TNPW060310K0BEEA" TNPW0603 31.876,50.975 r180 top value=10.0k (schematic designator R13)
R14_P1 "TNPW060310K0BEEA" TNPW0603 111.876,64.258 r180 top value=10.0k (schematic designator R14)
R14_P2 "TNPW060310K0BEEA" TNPW0603 71.876,64.258 r180 top value=10.0k (schematic designator R14)
R14_P3 "TNPW060310K0BEEA" TNPW0603 31.876,64.258 r180 top value=10.0k (schematic designator R14)
R15_P1 "TNPW060310K0BEEA" TNPW0603 111.876,84.411 r180 top value=10.0k (schematic designator R15)
R15_P2 "TNPW060310K0BEEA" TNPW0603 71.876,84.411 r180 top value=10.0k (schematic designator R15)
R15_P3 "TNPW060310K0BEEA" TNPW0603 31.876,84.411 r180 top value=10.0k (schematic designator R15)
R16_P1 "TNPW060310K0BEEA" TNPW0603 111.876,97.606 r180 top value=10.0k (schematic designator R16)
R16_P2 "TNPW060310K0BEEA" TNPW0603 71.876,97.606 r180 top value=10.0k (schematic designator R16)
R16_P3 "TNPW060310K0BEEA" TNPW0603 31.876,97.606 r180 top value=10.0k (schematic designator R16)
R17_P1 "RT0603DRE07160RL" 0603 85.72,112.886 r0 top value=160 (schematic designator R17)
R17_P2 "RT0603DRE07160RL" 0603 45.21,112.886 r0 top value=160 (schematic designator R17)
R17_P3 "RT0603DRE07160RL" 0603 5.72,112.886 r0 top value=160 (schematic designator R17)
U1_P1 "ACS772ECB-250B-PFF-T" FP-ACS772ECB-250B-PFF-T_PTH_10MM0_13MM0-MFG 99.5,120.25 r270 top (schematic designator U1)
U1_P2 "ACS772ECB-250B-PFF-T" FP-ACS772ECB-250B-PFF-T_PTH_10MM0_13MM0-MFG 59.458,120.25 r270 top (schematic designator U1)
U1_P3 "ACS772ECB-250B-PFF-T" FP-ACS772ECB-250B-PFF-T_PTH_10MM0_13MM0-MFG 19.453,120.25 r270 top (schematic designator U1)
ZZ1 "This Assembly Note is for PCB labels only" AssemblyNoteLabel 139,92.5 r0 top
ZZ2 "These assemblies are ESD sensitive, ESD precautions shall be observed." AssemblyNote 139,95.454 r0 top
ZZ3 "These assemblies must be clean and free from flux and all contaminants. Use of no clean flux is not acceptable." AssemblyNote 138.75,98.25 r0 top
ZZ4 "These assemblies must comply with workmanship standards IPC-A-610 Class 2, unless otherwise specified." AssemblyNote 138.75,101.057 r0 top

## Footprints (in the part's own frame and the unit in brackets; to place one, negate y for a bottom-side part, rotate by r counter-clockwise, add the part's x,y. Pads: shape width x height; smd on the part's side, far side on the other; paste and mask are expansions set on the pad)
0603 [mm] "0603 from SM-752 data"
  rect 1x0.95 smd: 1(-0.8,0) 2(0.8,0)
  silkscreen extent -1.52,-0.69 1.52,0.69, body extent -0.87,-0.47 0.87,0.47, height 1
AssemblyNote [mm] "Assembly Note"
AssemblyNoteLabel [mm] "Assembly Note for PCB Labels"
CE_Mark_5mm [mm] "Minimum text height for CE Mark"
  silkscreen extent -3.5,-2.5 3.5,2.5
FCC_disclaimer [mm]
Fiducial10-20 [mm]
  round 1 smd mask+0.5: 1(0,0)
  Top Layer keep-out circle w1.178: c0,0 r0.5
FP-7461098_TERM_REDCUBE_M6-MFG [mm]
  round 1.8 hole 1.475 paste-1000 mask+0: 1(-5.08,-5.08) 1(-5.08,-2.54) 1(-5.08,0) 1(-5.08,2.54) 1(-5.08,5.08) 1(-2.54,5.08) 1(-2.54,-2.54) 1(-2.54,0) 1(-2.54,2.54) 1(-2.54,-5.08) 1(0,5.08) 1(0,2.54) 1(0,0) 1(0,-2.54) 1(0,-5.08) 1(2.54,5.08) 1(2.54,-2.54) 1(2.54,0) 1(2.54,2.54) 1(2.54,-5.08) 1(5.08,-5.08) 1(5.08,-2.54) 1(5.08,0) 1(5.08,2.54) 1(5.08,5.08)
  silkscreen extent -6.6,-6.6 6.6,6.6, body extent -6.7,-6.7 6.7,6.7, height 0.25
FP-ACS772ECB-250B-PFF-T_PTH_10MM0_13MM0-MFG [mm]
  rrect7% 1.5x1.5 hole 0.8 paste-1000 mask+0: 1(-1.91,-9.59)
  round 1.5 hole 0.8 paste-1000 mask+0: 2(0,-9.59) 3(1.91,-9.59)
  rrect100% 6.6x2.6 hole 2 slot 6 at 0 deg paste-1000 mask+0: 4(5,11.809) 5(-5,11.809)
  round 5.4 smd paste-1000 mask+0: 4(5.099,11.809) 5(-5.25,11.809)
  round 5.4 smd far side paste-1000 mask+0: 4(5.099,11.809) 5(-5.25,11.809)
  Top Layer region: 0.5,13.468 1.581,14.453 3,14.809 3,14.809 7,14.81 8.302,14.512 9.345,13.68 9.925,12.477 9.925,11.142 9.345,9.939 8.302,9.107 7,8.809 7,8.809 3,8.809 1.581,9.166 0.5,10.151 0.5,10.151
  Top Layer region: -0.5,10.151 -1.581,9.166 -3,8.81 -3,8.81 -7,8.809 -8.302,9.107 -9.345,9.939 -9.925,11.142 -9.925,12.477 -9.345,13.68 -8.302,14.512 -7,14.809 -7,14.81 -3,14.81 -1.581,14.453 -0.5,13.468 -0.5,13.468
  Bottom Layer region: 0.5,13.468 1.581,14.453 3,14.809 3,14.809 7,14.81 8.302,14.512 9.345,13.68 9.925,12.477 9.925,11.142 9.345,9.939 8.302,9.107 7,8.809 7,8.809 3,8.809 1.581,9.166 0.5,10.151 0.5,10.151
  Bottom Layer region: -0.5,10.151 -1.581,9.166 -3,8.81 -3,8.81 -7,8.809 -8.302,9.107 -9.345,9.939 -9.925,11.142 -9.925,12.477 -9.345,13.68 -8.302,14.512 -7,14.809 -7,14.81 -3,14.81 -1.581,14.453 -0.5,13.468 -0.5,13.468
  silkscreen extent -5.05,-11.04 5.05,6.55, body extent -10.1,-10.44 10.1,14.91, height 0.25
FP-C4AQCBU4560A1XJ_RADIAL-MFG [mm]
  rrect6% 1.55x1.55 hole 1 paste-1000 mask+0: 1(-13.75,0)
  round 1.55 hole 1 paste-1000 mask+0: 2(13.75,0)
  silkscreen extent -16,-6.65 16,6.65, body extent -16.1,-6.75 16.1,6.75, height 0.25
FP-IAUT300N10S5N015ATMA1_HSOF-8-MFG [mm]
  rrect13% 0.8x2.8 smd paste-1000 mask+0: 1(-4.2,-5.25)
  round 0.837 smd paste-1000 mask+0: 2-3-4-5-6-7-8(0.625,-4.375)
  round 7.2 smd paste-1000 mask+0: 9(0,2.65)
  Top Layer region: -5.05,6.65 5.05,6.65 5.05,5.25 4.35,5.25 4.35,2.35 4.85,2.35 4.85,-1.35 -4.85,-1.35 -4.85,2.35 -4.35,2.35 -4.35,5.25 -5.05,5.25 -5.05,6.65
  Top Layer region: -3.4,-3.85 4.6,-3.85 4.6,-6.65 3.8,-6.65 3.8,-4.65 3.4,-4.65 3.4,-6.65 2.6,-6.65 2.6,-4.65 2.2,-4.65 2.2,-6.65 1.4,-6.65 1.4,-4.65 1,-4.65 1,-6.65 0.2,-6.65 0.2,-4.65 -0.2,-4.65 -0.2,-6.65 -1,-6.65 -1,-4.65 -1.4,-4.65 -1.4,-6.65 -2.2,-6.65 -2.2,-4.65 -2.6,-4.65 -2.6,-6.65 -3.4,-6.65 -3.4,-3.85
  silkscreen extent -5.05,-7.33 5.05,-1.73, body extent -5.15,-6.75 5.15,6.75, height 0.25
FP-RCS060310R0FKEA_0603-MFG [mm]
  rrect13% 0.75x1 smd paste+0 mask+0: 1(-0.75,0) 2(0.75,0)
  silkscreen extent -0.82,-0.86 0.87,0.86, body extent -1.22,-0.6 1.22,0.6, height 0.25
Label_650x200 [mil] "Thermal Transfer Label"
  round 1 on Mech13: 0(0,0)
  silkscreen extent -325,-100 325,100, body extent -325,-100 325,100, height 1
Samtec_TSM-103-01-x-SV-P [mm] "Header, 2.54mm, 3x1, SMT"
  rrect8% 1.27x3.43 smd: 1(-2.54,1.46) 2(0,-1.46) 3(2.54,1.46)
  silkscreen extent -4.1,-1.27 3.81,1.27, body extent -3.81,-2.41 3.81,2.41, height 9.97
TI_Stacked_Overlay_Small [mm]
  silkscreen extent -10.63,-2.49 10.63,2.49
TNPW0603 [mm] "Vishay"
  rect 0.5x0.9 smd: 1(-0.75,0) 2(0.75,0)
  silkscreen extent -0.2,-0.6 0.2,0.6, body extent -0.85,-0.47 0.85,0.47, height 0.55
WEEE_Minimum [mm] "WEEElie bin"
  silkscreen extent -2.42,-4.38 2.52,2.65

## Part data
C1_P1 C1_P2 C1_P3 C2_P1 C2_P2 C2_P3: library part CMP-0094169-1, "5.6 µF Film Capacitor - 650V Polypropylene (PP), Metallized Radial", Digikey Part Number=399-16962-ND, Manufacturer=KEMET, Mouser Part Number=80-C4AQCBU4560A1XJ, Operating Temperature Range="-55°C to +105°C", Tolerance_%=5%, ValueDisplayed=5.6uF
C3_P1 C3_P2 C3_P3 C4_P1 C4_P2 C4_P3: library part CMP-0006802-4, "CAP, CERM, 0.1 uF, 50 V, +/- 10%, X7R, 0603", Cap_Case=0603, Manufacturer=AVX, Supplier Part Number 1=478-5052-1-ND, TempCo=X7R, Tolerance_%=10%, Value1=Unknown, Value2=50V, ValueDisplayed=0.1uF
FID1 FID2 FID3: library part CMP-0077181-1, "Fiducial mark.  There is nothing to buy or mount.", Manufacturer=N/A
J1_P1 J1_P2 J1_P3 J3 J4: library part CMP-0093152-1, "Conn Terminal M 1 POS Press Fit ST 25 Terminal 1 Port", Current_A=250A, Digikey Part Number=732-3278-ND, Manufacturer="Wurth Electronics", Mouser Part Number=710-7461098, Operating Temperature Range="-55°C to +150°C"
J2_P1 J2_P2 J2_P3 J5_P1 J5_P2 J5_P3 J6_P1 J6_P2 J6_P3 J7: library part CMP-0055592-1, "Header, 2.54mm, 3x1, Gold, SMT", Color=Black, Current_A=5.4A, Manufacturer=Samtec, Supplier Part Number 1=TSM-103-01-L-SV-P-TR-ND, Voltage_V=475V
LBL1: library part CMP-0003625-1, "Thermal Transfer Printable Labels, 0.650\" W x 0.200\" H - 10,000 per roll", Manufacturer=Brady, Supplier Part Number 1=97C5133
Logo1: library part CMP-0074844-1
Logo2: library part CMP-0074838-1, "Texas Instrument Corporate Signature"
Logo3: library part CMP-0074847-1, "FCC_disclaimer"
Logo4: library part CMP-0074769-1
Q1_P1 Q1_P2 Q1_P3 Q2_P1 Q2_P2 Q2_P3 Q3_P1 Q3_P2 Q3_P3 Q4_P1 Q4_P2 Q4_P3 Q5_P1 Q5_P2 Q5_P3 Q6_P1 Q6_P2 Q6_P3 Q7_P1 Q7_P2 Q7_P3 Q8_P1 Q8_P2 Q8_P3: library part CMP-0120643-1, "100V 300A 1.5MOHM TOLL", Digikey Part Number=IAUT300N10S5N015ATMA1CT-ND, Drain To Source Breakdown Voltage=100V, Input Capacitace At Vds="12316pF @ 50V", Manufacturer=Infineon, Mouser Part Number=726-IAUT300N10S5N015, Operating Temperature Range="-55°C to +175°C", Power_W=375W, Pulse Drain Current=1200A, Typ Forward Diode Voltage=0.9V
R1_P1 R1_P2 R1_P3 R2_P1 R2_P2 R2_P3 R3_P1 R3_P2 R3_P3 R4_P1 R4_P2 R4_P3 R9_P1 R9_P2 R9_P3 R10_P1 R10_P2 R10_P3 R11_P1 R11_P2 R11_P3 R12_P1 R12_P2 R12_P3: library part CMP-0094869-1, "10 Ohms ±1% 0.25W, 1/4W Chip Resistor 0603 (1608 Metric) Automotive AEC-Q200, Pulse Withstanding Thick Film", Digikey Part Number=541-2781-1-ND, Manufacturer=Vishay, Mouser Part Number=71-RCS060310R0FKEA, Operating Temperature Range="-55°C to +155°C", Power_W=250mW, TempCo=100ppm/°C, Tolerance_%=1%
R5_P1 R5_P2 R5_P3 R6_P1 R6_P2 R6_P3 R7_P1 R7_P2 R7_P3 R8_P1 R8_P2 R8_P3 R13_P1 R13_P2 R13_P3 R14_P1 R14_P2 R14_P3 R15_P1 R15_P2 R15_P3 R16_P1 R16_P2 R16_P3: library part CMP-0025686-1, "RES, 10.0 k, 0.1%, 0.1 W, AEC-Q200 Grade 1, 0603", Manufacturer=Vishay-Dale, Power_W=100mW, Supplier Part Number 1=TNP10.0KAACT-ND, TempCo="25 ppm/C", Tolerance_%=0.1%, Value2=0.1W, Value_Code=10k0, ValueDisplayed=10.0k
R17_P1 R17_P2 R17_P3: library part CMP-0024720-2, "RES, 160, 0.5%, 0.1 W, 0603", Manufacturer="Yageo America", Power_W=100mW, TempCo="50 ppm/C", Tolerance_%=0.5%, Value2=0.1W, Value_Code=160R, ValueDisplayed=160
U1_P1 U1_P2 U1_P3: library part CMP-0120638-1, "Galvanically Isolated Current Sensor IC with 100 µΩ Current Conductor, Sensing Current 250A, Sensor Sensitivity 8mV/A", Current Sensitivity=8mV/A, Manufacturer="Allegro MicroSystems LLC", Max Sensing Current=250A, Max Supply Voltage=5.5V, Min Supply Voltage=4.5V, Operating Supply Current=10mA, Operating Temperature Range="-40°C to +85°C"
ZZ1: library part CMP-0003616-3
ZZ2: library part CMP-0077236-1
ZZ3: library part CMP-0077237-1
ZZ4: library part CMP-0077238-1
